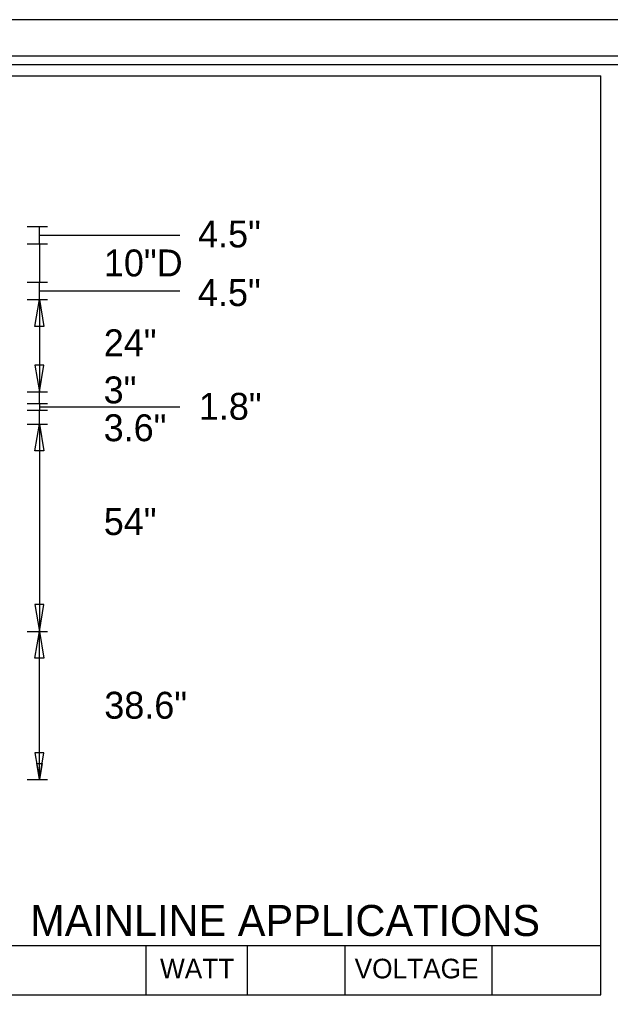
# Model space of a CAD drawing. Extents: x 17890628 to 17891459, y 17897314 to 17897992.
# Drawn here: x 17890753.03 to 17890765.84, y 17897475.46 to 17897496.82 of the extents above; entities that cross this region are included whole.
import ezdxf

# ---------------------------------------------------------------- set-up
doc = ezdxf.new("R2010")
doc.units = 0
for name, color, linetype in [('GSDims', 7, 'Continuous'), ('PlotBorder_dp', 7, 'Continuous'), ('SheetBorder_dp', 7, 'Continuous'), ('SheetLinesMisc2_dp', 7, 'Continuous'), ('TextMinor', 7, 'Continuous')]:
    doc.layers.add(name, color=color, linetype=linetype)

msp = doc.modelspace()

# ---------------------------------------------------------------- linework, layer by layer
at = {"layer": 'GSDims'}
for p, q in [((17890753.2, 17897492.33), (17890753.638, 17897492.33)), ((17890753.2, 17897492.33), (17890753.2, 17897492.33)), ((17890753.463, 17897491.955), (17890753.463, 17897492.33)), ((17890753.463, 17897492.143), (17890756.509, 17897492.143)), ((17890753.2, 17897491.955), (17890753.638, 17897491.955)), ((17890753.2, 17897491.955), (17890753.638, 17897491.955)), ((17890753.463, 17897491.955), (17890753.463, 17897491.122)), ((17890753.2, 17897491.122), (17890753.638, 17897491.122)), ((17890753.2, 17897491.122), (17890753.638, 17897491.122)), ((17890753.463, 17897490.747), (17890753.463, 17897491.122)), ((17890753.2, 17897490.747), (17890753.638, 17897490.747)), ((17890753.2, 17897490.747), (17890753.638, 17897490.747)), ((17890753.463, 17897490.934), (17890756.509, 17897490.934)), ((17890753.463, 17897490.747), (17890753.463, 17897488.743)), ((17890753.2, 17897488.743), (17890753.638, 17897488.743)), ((17890753.2, 17897488.743), (17890753.638, 17897488.743)), ((17890753.463, 17897488.493), (17890753.463, 17897488.743)), ((17890753.2, 17897488.493), (17890753.638, 17897488.493)), ((17890753.2, 17897488.493), (17890753.638, 17897488.493)), ((17890753.463, 17897488.493), (17890753.463, 17897488.347)), ((17890753.463, 17897488.42), (17890756.509, 17897488.42)), ((17890753.2, 17897488.347), (17890753.638, 17897488.347)), ((17890753.2, 17897488.347), (17890753.638, 17897488.347)), ((17890753.463, 17897488.046), (17890753.463, 17897488.347)), ((17890753.2, 17897488.046), (17890753.638, 17897488.046)), ((17890753.2, 17897488.046), (17890753.638, 17897488.046)), ((17890753.463, 17897488.046), (17890753.463, 17897483.547)), ((17890753.2, 17897483.547), (17890753.638, 17897483.547)), ((17890753.2, 17897483.547), (17890753.638, 17897483.547)), ((17890753.463, 17897480.33), (17890753.463, 17897483.547)), ((17890753.2, 17897480.33), (17890753.638, 17897480.33)), ((17890753.2, 17897480.33), (17890753.2, 17897480.33))]:
    msp.add_line(p, q, dxfattribs=at)
for points in [[(17890753.463, 17897490.747), (17890753.56, 17897490.164), (17890753.366, 17897490.164)], [(17890753.463, 17897488.743), (17890753.56, 17897489.326), (17890753.366, 17897489.326)], [(17890753.463, 17897488.046), (17890753.56, 17897487.462), (17890753.366, 17897487.462)], [(17890753.463, 17897483.547), (17890753.56, 17897484.13), (17890753.366, 17897484.13)], [(17890753.463, 17897483.547), (17890753.56, 17897482.963), (17890753.366, 17897482.963)], [(17890753.463, 17897480.33), (17890753.56, 17897480.914), (17890753.366, 17897480.914)], [(17890753.463, 17897480.33), (17890753.405, 17897480.68), (17890753.521, 17897480.68)]]:
    msp.add_lwpolyline(points, close=True, dxfattribs=at)
at = {"layer": 'PlotBorder_dp'}
msp.add_lwpolyline([(17890701.346, 17897413.687), (17890830.745, 17897413.687), (17890830.745, 17897496.818), (17890701.346, 17897496.818)], close=True, dxfattribs=at)
at = {"layer": 'SheetBorder_dp'}
msp.add_line((17890705.659, 17897496.034), (17890826.432, 17897496.034), dxfattribs=at)
at = {"layer": 'SheetLinesMisc2_dp'}
for p, q in [((17890705.872, 17897495.849), (17890826.223, 17897495.849)), ((17890724.706, 17897495.599), (17890765.638, 17897495.599)), ((17890765.638, 17897475.661), (17890765.638, 17897495.599)), ((17890724.706, 17897476.729), (17890765.638, 17897476.729)), ((17890755.773, 17897476.729), (17890755.773, 17897475.661)), ((17890757.969, 17897476.729), (17890757.969, 17897475.661)), ((17890760.087, 17897476.729), (17890760.087, 17897475.661)), ((17890763.275, 17897476.729), (17890763.275, 17897475.661)), ((17890724.706, 17897475.661), (17890765.638, 17897475.661))]:
    msp.add_line(p, q, dxfattribs=at)

# ---------------------------------------------------------------- texts
at = {"layer": 'GSDims'}
for s, height, p in [('4.5"', 0.5833, (17890756.903, 17897491.878)), ('10"D', 0.5833, (17890754.861, 17897491.249)), ('4.5"', 0.5833, (17890756.901, 17897490.606)), ('24"', 0.5833, (17890754.858, 17897489.517)), ('3"', 0.5833, (17890754.855, 17897488.494)), ('1.8"', 0.5833, (17890756.92, 17897488.138)), ('3.6"', 0.5833, (17890754.855, 17897487.673)), ('54"', 0.5833, (17890754.858, 17897485.638)), ('38.6"', 0.5833, (17890754.869, 17897481.653)), ('MAINLINE APPLICATIONS', 0.67331, (17890753.261, 17897476.938))]:
    msp.add_text(s, height=height, dxfattribs=at).set_placement(p)
at = {"layer": 'TextMinor'}
for s, p in [('WATT', (17890756.078, 17897476.019)), ('VOLTAGE', (17890760.299, 17897476.019))]:
    msp.add_text(s, height=0.4252, dxfattribs=at).set_placement(p)

doc.saveas('drawing.dxf')
